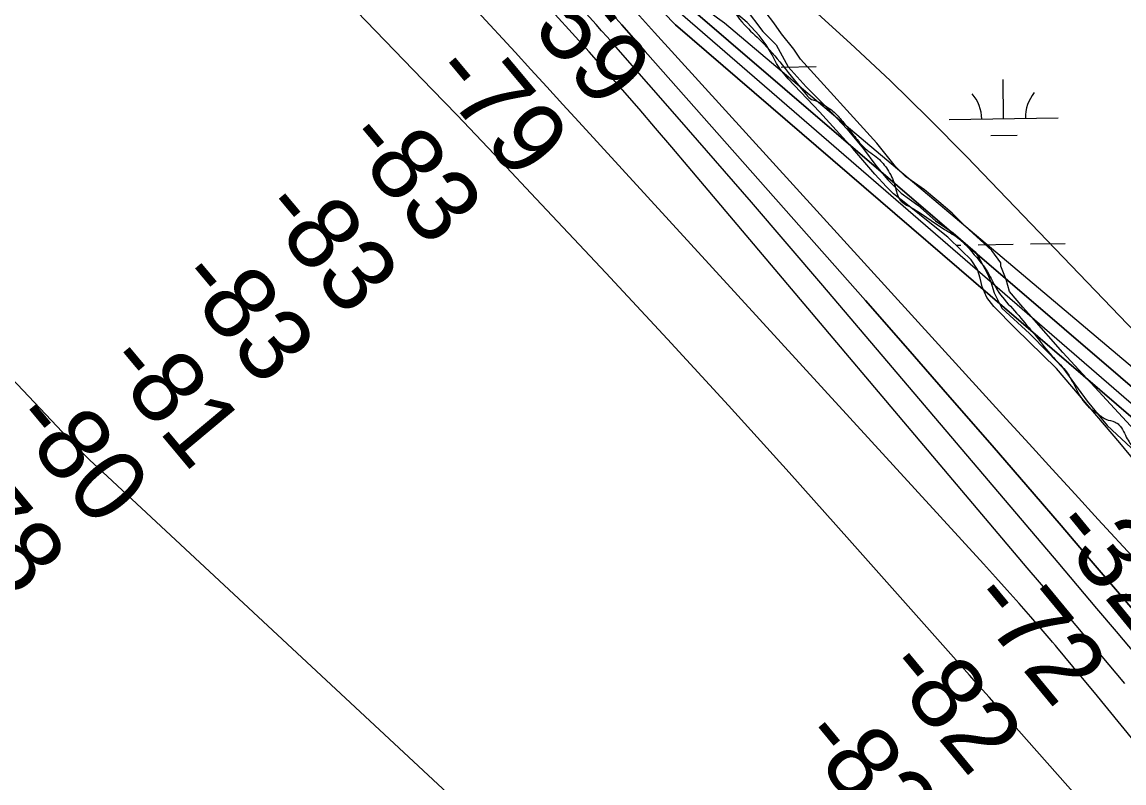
# Model space of a CAD drawing. Extents: x 3887375 to 3925618, y 296674 to 322633.
# Drawn here: x 3897913 to 3898925, y 309507 to 310205 of the extents above; entities that cross this region are included whole.
import ezdxf

# ---------------------------------------------------------------- set-up
doc = ezdxf.new("R2010")
doc.units = 0
for name, color, linetype in [('V-RIVR-EDGE', 7, 'Continuous'), ('V-RIVR-JETY', 7, 'Continuous'), ('V-RIVR-RANG', 7, 'Continuous'), ('V-TOPO-DPTH', 7, 'Continuous'), ('V-TOPO-MAJR', 7, 'Continuous'), ('V-TOPO-MINR', 7, 'Continuous'), ('V-TOPO-WATR', 7, 'Continuous'), ('V-WETL-SWMP', 7, 'Continuous')]:
    doc.layers.add(name, color=color, linetype=linetype)

msp = doc.modelspace()

# ---------------------------------------------------------------- linework, layer by layer
at = {"layer": 'V-RIVR-EDGE'}
for points in [[(3896115.8, 312736.3), (3896123.6, 312723.7), (3896129.9, 312714.4), (3896135.6, 312703.7), (3896139.5, 312690.4), (3896139.8, 312681.4), (3896138.2, 312674.8), (3896136.8, 312674.1), (3896128.5, 312683.1), (3896119.6, 312696.5), (3896111.3, 312706.8), (3896107.3, 312707.8), (3896105, 312706.5), (3896104.3, 312701.1), (3896107.9, 312688.8), (3896111.2, 312681.2), (3896123.5, 312667.2), (3896140.7, 312647.2), (3896161, 312617.2), (3896188.5, 312584.9), (3896210, 312563.2), (3896237.6, 312538.5), (3896253.5, 312524.9), (3896271.4, 312512.5), (3896287.7, 312501.8), (3896299, 312494.8), (3896307, 312486.8), (3896325.8, 312456.2), (3896335.8, 312438.5), (3896350.7, 312424.2), (3896373.6, 312404.5), (3896404.8, 312381.8), (3896442, 312359.5), (3896468.9, 312343.4), (3896491.1, 312332.4), (3896500.1, 312327.1), (3896508.4, 312318.7), (3896515.3, 312306.4), (3896528.3, 312284.4), (3896534.9, 312271.8), (3896552.8, 312258.8), (3896583, 312239.7), (3896613.6, 312220), (3896639.8, 312198.7), (3896665.3, 312175.7), (3896698.5, 312153), (3896718.4, 312139), (3896747, 312114.6), (3896768.2, 312094.3), (3896793.7, 312068.3), (3896812.7, 312048.3), (3896828.9, 312030), (3896844.5, 312006.3), (3896867.4, 311982.3), (3896895.9, 311956), (3896949, 311910), (3896976.5, 311885.6), (3896985.2, 311878.6), (3896997.8, 311872.9), (3897005.4, 311870.2), (3897020, 311862.9), (3897041.6, 311845.9), (3897061.2, 311830.9), (3897070.1, 311823.9), (3897078.8, 311813.9), (3897087.7, 311797.5), (3897092.3, 311785.6), (3897097, 311776.9), (3897111.2, 311756.3), (3897119.5, 311747.3), (3897129.5, 311738.6), (3897149.4, 311722.6), (3897170.9, 311704.6), (3897186.2, 311690.6), (3897201.8, 311670.2), (3897228.6, 311633.3), (3897264.7, 311581.6), (3897280, 311565), (3897305.2, 311540), (3897328.4, 311515.6), (3897360.9, 311485.9), (3897388.8, 311458.3), (3897419.3, 311434.3), (3897433.9, 311420.3), (3897454.5, 311394.6), (3897475, 311368.3), (3897490.6, 311354.6), (3897505.6, 311336.6), (3897515.8, 311319.6), (3897527.8, 311305.3), (3897546.7, 311288.3), (3897564.6, 311280.6), (3897578.2, 311271.3), (3897592.8, 311257.9), (3897613.1, 311238.6), (3897630.3, 311218.9), (3897644.6, 311200.6), (3897648.9, 311196.6), (3897654.9, 311195.9), (3897664.8, 311187.9), (3897681.4, 311173.9), (3897696, 311156.2), (3897728.2, 311123.2), (3897747.7, 311099.3), (3897753.7, 311088.3), (3897756.7, 311085.6), (3897762.6, 311082.9), (3897779.6, 311067.6), (3897798.5, 311046.9), (3897815.4, 311028.6), (3897832, 311014.6), (3897852.2, 310999.9), (3897867.8, 310985.6), (3897880.8, 310970.2), (3897894, 310949.2), (3897907.6, 310928.6), (3897922.2, 310908.3), (3897948, 310879.6), (3897967.3, 310856.6), (3897987.8, 310835.3), (3898011.7, 310813.3), (3898048.6, 310785.3), (3898064.5, 310774.2), (3898081.4, 310759.2), (3898099.7, 310738.9), (3898112.9, 310724.6), (3898123.2, 310708.6), (3898130.8, 310696.3), (3898136.8, 310688.9), (3898147.4, 310677.3), (3898160, 310664.3), (3898168.9, 310655.3), (3898196.5, 310623.6), (3898206.1, 310609.3), (3898214, 310600.6), (3898230.3, 310582), (3898242.2, 310565.3), (3898262.4, 310541.3), (3898281.7, 310521.3), (3898296.6, 310506), (3898340.4, 310470.3), (3898350, 310459.3), (3898357, 310445.3), (3898373.6, 310426), (3898390.1, 310409.6), (3898399.4, 310404.6), (3898413.4, 310395.3), (3898421.7, 310387.3), (3898430, 310378.6), (3898436.6, 310363.3), (3898463.4, 310334.6), (3898482.3, 310314.6), (3898496.6, 310298.3), (3898513.2, 310279.7), (3898535.7, 310254.7), (3898547.3, 310242), (3898560.3, 310224.7), (3898576.5, 310203), (3898592.1, 310187.7), (3898611.3, 310166), (3898633.5, 310138.7), (3898638.2, 310134.4), (3898642.5, 310133), (3898652.1, 310127.7), (3898657.8, 310123.7), (3898665.4, 310115.7), (3898676.7, 310101.7), (3898686, 310090.7), (3898692.6, 310085.3), (3898699.2, 310080.3), (3898707.9, 310070), (3898714.5, 310056.4), (3898718.4, 310043.7), (3898720.4, 310041), (3898727.4, 310036.4), (3898760.3, 310015), (3898774.2, 310006), (3898785.5, 309994.3), (3898801.4, 309973.3), (3898808.7, 309959.4), (3898822.6, 309942.4), (3898837.9, 309924.7), (3898844.8, 309916.4), (3898858.7, 309899), (3898871.4, 309885.4), (3898894.5, 309850.4), (3898899.9, 309846.7), (3898908.5, 309840.7), (3898917.1, 309838), (3898920.4, 309835.7), (3898928.1, 309822.7), (3898935.4, 309812.7), (3898943.6, 309802.7), (3898951.9, 309787.7), (3898962.9, 309772.4), (3898972.5, 309757.4), (3898979.1, 309752.4), (3898987.1, 309749.1), (3898990.7, 309745.1), (3899002, 309727.8), (3899013.3, 309715.4), (3899031.2, 309696.4), (3899044.8, 309680.1), (3899055.7, 309665.5), (3899065, 309653.8), (3899074.6, 309640.1), (3899085.5, 309630.8), (3899093.8, 309628.1), (3899099.2, 309628.1), (3899103.2, 309626.1), (3899108.1, 309616.1), (3899114.7, 309606.4), (3899123.7, 309591.1), (3899128.3, 309582.8), (3899128.3, 309580.5), (3899127.6, 309569.2), (3899127.9, 309565.8), (3899132.9, 309561.5), (3899159.8, 309529.2), (3899191, 309497.2), (3899204.9, 309480.5), (3899212.2, 309470.2), (3899224.8, 309457.2), (3899244.7, 309437.5), (3899252.6, 309429.9), (3899261.9, 309422.9), (3899272.6, 309415.8), (3899279.5, 309406.5), (3899287.5, 309396.2), (3899300.1, 309376.5), (3899311.3, 309362.5), (3899327.9, 309343.2), (3899342.2, 309325.6), (3899360.1, 309304.6), (3899377.3, 309282.9), (3899414.5, 309240.6), (3899433.4, 309219.6), (3899447.3, 309203.9), (3899464.5, 309184.9), (3899479.1, 309166.9), (3899493.4, 309149.9)], [(3894498, 310522.4), (3894530, 310496.1), (3894553.8, 310474.7), (3894579.9, 310451.3), (3894614.8, 310419.2), (3894633.2, 310400.7), (3894662.8, 310372.4), (3894685.1, 310353.4), (3894692.4, 310347.1), (3894709.8, 310328.1), (3894746.6, 310285.3), (3894785.8, 310252.2), (3894809.6, 310225.9), (3894830.4, 310205.4), (3894852.7, 310189.9), (3894866.7, 310171.8), (3894915.2, 310120.3), (3894950.1, 310083.7), (3894971.4, 310062.8), (3894999, 310039.4), (3895025.2, 310017), (3895052.8, 309992.7), (3895093, 309952.3), (3895110.9, 309932.8), (3895141.4, 309903.1), (3895188.9, 309855.9), (3895222.8, 309821.3), (3895255.8, 309784.3), (3895319.2, 309722.5), (3895350.7, 309688.4), (3895358.4, 309676.3), (3895364.7, 309669.4), (3895374.9, 309663.1), (3895389, 309650.4), (3895410.8, 309628.1), (3895448.5, 309583.3), (3895480.5, 309554.1), (3895503.8, 309527.8), (3895533.8, 309499.5), (3895577.4, 309454.8), (3895606.9, 309425.5), (3895653.5, 309378.8), (3895685.9, 309349.1), (3895719.8, 309314.5), (3895749.4, 309285.8), (3895790.6, 309242.5), (3895837.1, 309195.8), (3895863.7, 309164.1), (3895900, 309127.6), (3895944.1, 309081.4), (3895955.7, 309070.7), (3895974.6, 309054.6), (3896002.3, 309033.1), (3896032.8, 309003.9), (3896062.8, 308972.3), (3896082.7, 308950.4), (3896119.5, 308911.9), (3896139.3, 308892.5), (3896152, 308889.5), (3896163.1, 308883.7), (3896167.9, 308873.9), (3896170.3, 308862.3), (3896184.4, 308844.3), (3896211, 308816), (3896224.1, 308810.2), (3896236.7, 308802.4), (3896249.8, 308786.8), (3896255.6, 308776.6), (3896270.6, 308766.4), (3896280.3, 308753.2), (3896295.8, 308737.2), (3896375.3, 308661.2), (3896425.2, 308610.1), (3896464.4, 308570.6), (3896519.6, 308515.6), (3896548.7, 308483), (3896563.2, 308467.5), (3896597.6, 308430.9), (3896635.9, 308396.4), (3896666.4, 308365.7), (3896681.4, 308349.6), (3896712.4, 308320.4), (3896746.3, 308287.3), (3896777.4, 308260), (3896801.6, 308235.7), (3896820.5, 308215.3), (3896842.8, 308195.3), (3896851.5, 308181.2), (3896882.5, 308148.6), (3896918.8, 308116.4), (3896962.9, 308074.6), (3896997.8, 308033.2), (3897029.2, 307998.6), (3897042.3, 307985), (3897083.5, 307945.6), (3897107.2, 307918.3), (3897123.2, 307898.8), (3897130, 307898.8), (3897142.1, 307893), (3897146, 307882.3), (3897149.9, 307874), (3897162.9, 307860.4), (3897188.6, 307833.1), (3897229.3, 307788.8), (3897267.6, 307752.3), (3897300.5, 307715.8), (3897334.4, 307680.3), (3897361.5, 307651.1), (3897384.8, 307628.2), (3897411.4, 307599), (3897445.8, 307563.4), (3897494.3, 307516.7), (3897543.2, 307462.7), (3897584.8, 307418.4), (3897609, 307394), (3897646.8, 307355.6), (3897678.8, 307323.9), (3897715.1, 307290.3), (3897752, 307253.3), (3897767, 307236.3), (3897837.7, 307158.4), (3897886.6, 307104.4), (3897936, 307048.4), (3897965.5, 307015.3), (3898010.6, 306970.1), (3898027.5, 306949.1), (3898045, 306936), (3898063.9, 306914.1), (3898089, 306882.5), (3898117.1, 306854.7), (3898160.2, 306801.2), (3898195.6, 306763.7), (3898235.8, 306719.9), (3898261.5, 306693.6), (3898297.3, 306650.8), (3898332.7, 306612.3), (3898369.9, 306568), (3898397.5, 306534.9), (3898422.2, 306505.8), (3898462.9, 306455.1), (3898495.3, 306417.2), (3898522, 306382.2), (3898601.4, 306284.3), (3898652.2, 306228.4), (3898693.4, 306177.3), (3898729.7, 306130.6), (3898777.1, 306074.1), (3898825.5, 306014.3), (3898848.8, 305986), (3898904, 305917.4), (3898957.2, 305854.7), (3898984.4, 305818.2), (3899049.7, 305744.7), (3899107.8, 305679.4), (3899129.1, 305651.7), (3899142.7, 305630.3), (3899156.2, 305611.8), (3899175.1, 305588), (3899224, 305529.6), (3899256, 305493.6), (3899288.9, 305449.3), (3899312.6, 305415.2), (3899375.6, 305336.9), (3899410.9, 305296), (3899442.8, 305252.2), (3899470.4, 305211.9), (3899531.4, 305133.5), (3899579.3, 305071.2), (3899616.1, 305026), (3899647.1, 304986.1), (3899690.7, 304931.1), (3899729.4, 304876.6), (3899753.6, 304846.9), (3899770.6, 304821.6), (3899817.5, 304755.5), (3899845.6, 304713.2), (3899868.3, 304677.2), (3899889.6, 304650.4), (3899911.4, 304623.6), (3899955.4, 304569.1), (3899987.4, 304526.8), (3900012.6, 304494.2), (3900025.6, 304476.2), (3900037.2, 304456.8), (3900061.9, 304431.9), (3900070.7, 304424.1), (3900074.5, 304414.4), (3900075, 304404.2), (3900073, 304397.9), (3900071.5, 304388.7), (3900071.5, 304383.8), (3900075.9, 304379), (3900087.1, 304374.1), (3900096.3, 304367.7), (3900108.4, 304362.4), (3900117.1, 304353.6), (3900140.8, 304326.3), (3900165.5, 304299.1), (3900226.1, 304227.6), (3900277.9, 304164.3), (3900320, 304105.9), (3900352.4, 304062.6), (3900384.4, 304023.2), (3900411.5, 303988.2), (3900438.1, 303954.1), (3900462.8, 303926.8), (3900556.2, 303812.5), (3900597.9, 303762.9), (3900633.7, 303716.6), (3900652.6, 303691.3), (3900702, 303626.6), (3900774.6, 303530.8), (3900849.1, 303437.3), (3900903.4, 303371.2), (3900928.1, 303343.4), (3900948.9, 303317.6), (3901001.2, 303258.3), (3901038.9, 303216.9), (3901074.8, 303173.1), (3901092.2, 303147.3), (3901171.6, 303050.5), (3901205, 303008.6), (3901238.4, 302968.2), (3901274.7, 302927.8), (3901303.3, 302893.8), (3901344, 302847.5), (3901366.7, 302816.4), (3901404.5, 302770.2), (3901454.4, 302715.2), (3901507.2, 302659.2), (3901551.7, 302608.1), (3901584.7, 302570.6), (3901650, 302491.3), (3901681, 302443.6), (3901717.8, 302388.2), (3901785.5, 302298.2), (3901789.5, 302293.3)]]:
    msp.add_spline(points, degree=3, dxfattribs=at)
at = {"layer": 'V-RIVR-JETY'}
for points in [[(3898577.2, 310218.1), (3898593.4, 310196.7), (3898605.6, 310184.5), (3898616.8, 310164.2), (3898633.1, 310145.9), (3898652.4, 310126.6), (3898670.7, 310107.3), (3898685.9, 310089), (3898697.1, 310073.7), (3898708.3, 310060.5), (3898720.5, 310048.3), (3898735.7, 310037.2), (3898752, 310022.9), (3898768.2, 310011.8), (3898788.5, 309994.5), (3898792.6, 309987.4), (3898799.7, 309974.2), (3898802.8, 309967), (3898805.8, 309956.9), (3898812.9, 309942.7), (3898838.3, 309919.3), (3898855.6, 309902), (3898868.8, 309887.8), (3898891.2, 309857.3), (3898909.5, 309834.9), (3898931.8, 309814.6)], [(3898942, 309822.7), (3898868.8, 309902), (3898840.4, 309934.5), (3898832.2, 309943.7), (3898820, 309957.9), (3898817, 309969.1), (3898811.9, 309981.3), (3898811.9, 309984.3), (3898803.8, 309995.5), (3898779.4, 310017.9), (3898767.2, 310030), (3898755, 310040.2), (3898741.8, 310051.4), (3898735.7, 310055.5), (3898724.5, 310063.6), (3898715.4, 310072.7), (3898698.1, 310094.1), (3898628, 310171.3), (3898621.9, 310180.5), (3898610.7, 310194.7), (3898603.6, 310204.8), (3898596.5, 310214)]]:
    msp.add_lwpolyline(points, dxfattribs=at)
at = {"layer": 'V-TOPO-DPTH'}
for points in [[(3898945.1, 309652), (3898919.2, 309682.5), (3898893.2, 309712.8), (3898867.3, 309743.1), (3898842.5, 309772), (3898803.9, 309816.6), (3898765.3, 309861.1), (3898726.5, 309905.5), (3898687.6, 309949.8), (3898485.5, 310178.5), (3898474.7, 310190.7), (3898463.9, 310202.9), (3898453, 310215.1), (3898442.1, 310227.3), (3898384.5, 310291.4), (3898344.7, 310335.6), (3898304.9, 310379.8), (3898265, 310423.8), (3898225, 310467.8), (3897965.8, 310752.8)], [(3897965.8, 310752.8), (3898225, 310467.8), (3898265, 310423.8), (3898304.9, 310379.8), (3898344.7, 310335.6), (3898384.5, 310291.4), (3898442.1, 310227.3), (3898453, 310215.1), (3898463.9, 310202.9), (3898474.7, 310190.7), (3898485.5, 310178.5), (3898687.6, 309949.8), (3898726.5, 309905.5), (3898765.3, 309861.1), (3898803.9, 309816.6), (3898842.5, 309772), (3898867.3, 309743.1), (3898893.2, 309712.8), (3898919.2, 309682.5), (3898945.1, 309652)], [(3899686.2, 308933.2), (3899549.1, 309098.8), (3899533, 309118.6), (3899517.2, 309138.6), (3899501.6, 309159), (3899486.4, 309179.5), (3899361.7, 309350.3), (3899308.5, 309422.5), (3899255, 309494.5), (3899200.9, 309566), (3899146.4, 309637.2), (3899056.5, 309753.8), (3899046.5, 309766.3), (3899036.2, 309778.6), (3899025.5, 309790.5), (3898510.2, 310233), (3898505.7, 310237.7), (3898501.2, 310242.5), (3898496.8, 310247.3), (3898150, 310629.3)], [(3898150, 310629.3), (3898496.8, 310247.3), (3898501.2, 310242.5), (3898505.7, 310237.7), (3898510.2, 310233), (3899025.5, 309790.5), (3899036.2, 309778.6), (3899046.5, 309766.3), (3899056.5, 309753.8), (3899146.4, 309637.2), (3899200.9, 309566), (3899255, 309494.5), (3899308.5, 309422.5), (3899361.7, 309350.3), (3899486.4, 309179.5), (3899501.6, 309159), (3899517.2, 309138.6), (3899533, 309118.6), (3899549.1, 309098.8), (3899686.2, 308933.2)], [(3898936, 309711.3), (3898901.5, 309748.8), (3898880.4, 309771.8), (3898859.2, 309794.9), (3898838.1, 309818), (3898817, 309841.1), (3898494.1, 310195.7), (3898477.4, 310214.2), (3898460.7, 310232.7), (3898444, 310251.2), (3898356.1, 310348.9), (3898295.4, 310416.1), (3898234.6, 310483.3), (3898173.6, 310550.2), (3898112.4, 310617.1)], [(3898112.4, 310617.1), (3898173.6, 310550.2), (3898234.6, 310483.3), (3898295.4, 310416.1), (3898356.1, 310348.9), (3898444, 310251.2), (3898460.7, 310232.7), (3898477.4, 310214.2), (3898494.1, 310195.7), (3898817, 309841.1), (3898838.1, 309818), (3898859.2, 309794.9), (3898880.4, 309771.8), (3898901.5, 309748.8), (3898936, 309711.3)], [(3899016.7, 309835.9), (3898780.7, 310081.6), (3898745.8, 310117), (3898710.3, 310151.8), (3898674, 310185.8), (3898637.1, 310219.1), (3898591.8, 310259), (3898577.1, 310272), (3898562.5, 310285), (3898547.9, 310298.1), (3898533.4, 310311.2), (3898468.4, 310370), (3898421.4, 310412.5), (3898374.4, 310455), (3898327.3, 310497.4), (3898280.2, 310539.9), (3898226.5, 310588.3)], [(3898165.3, 310585.9), (3898212.4, 310534.2), (3898259.4, 310482.3), (3898470, 310249.3), (3898480.7, 310237.5), (3898491.4, 310225.9), (3898502.3, 310214.3), (3898513.2, 310202.8), (3898975.1, 309805.6)], [(3898165.3, 310585.9), (3898212.4, 310534.2), (3898259.4, 310482.3), (3898470, 310249.3), (3898480.7, 310237.5), (3898491.4, 310225.9), (3898502.3, 310214.3), (3898513.2, 310202.8), (3898975.1, 309805.6)]]:
    msp.add_lwpolyline(points, dxfattribs=at)
at = {"layer": 'V-TOPO-MAJR'}
msp.add_lwpolyline([(3898936, 309624.8), (3898918.2, 309645.9), (3898900.3, 309666.9), (3898882.4, 309688), (3898864.5, 309709.1), (3898648.6, 309963.4), (3898615.9, 310001.7), (3898583, 310040), (3898550, 310078.1), (3898516.9, 310116), (3898460.6, 310180.3), (3898455.6, 310186.1), (3898450.5, 310191.8), (3898445.4, 310197.5), (3898440.3, 310203.2), (3898413.2, 310233.5), (3898394.5, 310254.3), (3898375.8, 310275.1), (3898357.1, 310295.9), (3898338.4, 310316.6), (3897943.8, 310754.4)], dxfattribs=at)
at = {"layer": 'V-TOPO-MINR'}
for points in [[(3898945.1, 309652), (3898919.2, 309682.5), (3898893.2, 309712.8), (3898867.3, 309743.1), (3898842.5, 309772), (3898803.9, 309816.6), (3898765.3, 309861.1), (3898726.5, 309905.5), (3898687.6, 309949.8), (3898485.5, 310178.5), (3898474.7, 310190.7), (3898463.9, 310202.9), (3898453, 310215.1), (3898442.1, 310227.3), (3898384.5, 310291.4), (3898344.7, 310335.6), (3898304.9, 310379.8), (3898265, 310423.8), (3898225, 310467.8), (3897965.8, 310752.8)], [(3899015.4, 309818.8), (3898558.3, 310204.4), (3898551.9, 310209), (3898545.6, 310213.7), (3898544.6, 310214.4), (3898539, 310218.9), (3898533.5, 310223.5), (3898528.2, 310228.4), (3898523.1, 310233.5), (3898515.4, 310241.4), (3898513.1, 310243.8), (3898510.8, 310246.3), (3898095.6, 310702.3)], [(3899686.2, 308933.2), (3899549.1, 309098.8), (3899533, 309118.6), (3899517.2, 309138.6), (3899501.6, 309159), (3899486.4, 309179.5), (3899361.7, 309350.3), (3899308.5, 309422.5), (3899255, 309494.5), (3899200.9, 309566), (3899146.4, 309637.2), (3899056.5, 309753.8), (3899046.5, 309766.3), (3899036.2, 309778.6), (3899025.5, 309790.5), (3898510.2, 310233), (3898505.7, 310237.7), (3898501.2, 310242.5), (3898496.8, 310247.3), (3898150, 310629.3)], [(3899238.1, 309092), (3898819.1, 309565.3), (3898810.1, 309575.4), (3898801.2, 309585.5), (3898792.2, 309595.6), (3898783.3, 309605.7), (3898673.1, 309729.8), (3898617.7, 309791.7), (3898562, 309853.3), (3898505.8, 309914.3), (3898449.2, 309975.1), (3898380.5, 310048.3), (3898358, 310072.2), (3898335.4, 310096), (3898312.7, 310119.8), (3898289.9, 310143.5), (3898203.3, 310233.4), (3898137.5, 310302.3), (3898072.1, 310371.6), (3898007.4, 310441.5), (3897943.1, 310511.8), (3897848, 310616.9)], [(3898936, 309711.3), (3898901.5, 309748.8), (3898880.4, 309771.8), (3898859.2, 309794.9), (3898838.1, 309818), (3898817, 309841.1), (3898494.1, 310195.7), (3898477.4, 310214.2), (3898460.7, 310232.7), (3898444, 310251.2), (3898356.1, 310348.9), (3898295.4, 310416.1), (3898234.6, 310483.3), (3898173.6, 310550.2), (3898112.4, 310617.1)], [(3898926, 309598.1), (3898903.6, 309624.6), (3898881.1, 309651.2), (3898858.7, 309677.8), (3898836.2, 309704.3), (3898525, 310072.7), (3898510, 310090.4), (3898494.9, 310108), (3898479.8, 310125.6), (3898464.6, 310143.1), (3898449.3, 310160.6), (3898433.9, 310178), (3898418.3, 310195.2), (3898402.7, 310212.4), (3898050.8, 310595.8)], [(3899818.9, 308745.4), (3899546.6, 309073.5), (3899524.8, 309100.4), (3899503.3, 309127.5), (3899482.4, 309155), (3899461.8, 309182.9), (3899222.5, 309512.5), (3899190.6, 309556.1), (3899158.5, 309599.5), (3899126, 309642.7), (3899093.2, 309685.7), (3899039.4, 309755.7), (3899033.3, 309763.4), (3899026.9, 309771), (3899020.4, 309778.3), (3898506.2, 310223.5), (3898498.5, 310231.7), (3898490.8, 310240), (3898483.3, 310248.3), (3898204.6, 310556), (3898167.8, 310596.5)], [(3898975.1, 309805.6), (3898513.2, 310202.8), (3898502.3, 310214.3), (3898491.4, 310225.9), (3898480.7, 310237.5), (3898470, 310249.3), (3898259.4, 310482.3), (3898212.4, 310534.2), (3898165.3, 310585.9)], [(3898934.7, 309544.7), (3898922.5, 309559.7), (3898910.3, 309574.7), (3898897.9, 309589.7), (3898885.6, 309604.7), (3898863.5, 309631.3), (3898862.1, 309632.9), (3898859.4, 309636.1), (3898858.1, 309637.6), (3898839.4, 309659.2), (3898828.7, 309671.4), (3898817.9, 309683.7), (3898807, 309695.8), (3898796, 309707.9), (3898424.5, 310113.8), (3898409.9, 310129.8), (3898395.2, 310145.8), (3898380.5, 310161.8), (3898365.9, 310177.8), (3898296.9, 310252.8)], [(3897601.1, 310198.2), (3897945.3, 309834.1), (3897949.7, 309829.5), (3897954.1, 309824.9), (3897958.5, 309820.3), (3897963, 309815.7), (3897968.4, 309810.2), (3897970.2, 309808.4), (3897973.7, 309804.9), (3897975.5, 309803.2), (3897979.1, 309799.7), (3897982.8, 309796.3), (3898357.6, 309447.4)]]:
    msp.add_lwpolyline(points, dxfattribs=at)
at = {"layer": 'V-TOPO-WATR'}
msp.add_lwpolyline([(3899016.7, 309835.9), (3898780.7, 310081.6), (3898745.8, 310117), (3898710.3, 310151.8), (3898674, 310185.8), (3898637.1, 310219.1), (3898591.8, 310259), (3898577.1, 310272), (3898562.5, 310285), (3898547.9, 310298.1), (3898533.4, 310311.2), (3898468.4, 310370), (3898421.4, 310412.5), (3898374.4, 310455), (3898327.3, 310497.4), (3898280.2, 310539.9), (3898226.5, 310588.3)], dxfattribs=at)
at = {"layer": 'V-WETL-SWMP'}
for p, q in [((3898610.4, 310163.9), (3898642.4, 310164.5)), ((3898814.6, 310116.7), (3898814, 310152.7)), ((3898764.6, 310115.8), (3898864.6, 310117.5)), ((3898802.9, 310101.1), (3898826.9, 310101.5)), ((3898791.2, 310000.8), (3898823.2, 310001.4)), ((3898839.2, 310001.7), (3898871.2, 310002.2)), ((3898771, 310000.5), (3898775.2, 310000.6))]:
    msp.add_line(p, q, dxfattribs=at)
msp.add_lwpolyline([(3898984.7, 309742.2), (3898921.3, 309819), (3898863.2, 309887.2), (3898825.3, 309924.3), (3898805.7, 309944.1), (3898799.2, 309952.5), (3898794.8, 309962.3), (3898792.9, 309970.1), (3898790.7, 309978.1), (3898784.9, 309987), (3898775.9, 309995.8), (3898763.2, 310007.9), (3898748.2, 310019.7), (3898724.7, 310038.7), (3898713.4, 310047.8), (3898706.9, 310054.2), (3898696.3, 310065.8), (3898676.2, 310089.2), (3898645.4, 310123.1), (3898616.8, 310153.3), (3898609.6, 310161.8), (3898605.9, 310167.5), (3898601.9, 310175.2), (3898596.6, 310184.6), (3898590.1, 310193.2), (3898579, 310205.1), (3898559.6, 310221.4)], dxfattribs=at)
for centre, start, end in [((3898759.3, 310116.2), 0.2115, 41.7552), ((3898869.8, 310118.1), 140.2115, 181.7552)]:
    msp.add_arc(centre, 35.2, start, end, dxfattribs=at)

# ---------------------------------------------------------------- texts
at = {"layer": 'V-RIVR-RANG'}
for s, rotation, p in [('-59', 309.8958, (3898361.6, 310222.1)), ('-79', 309.8958, (3898285.8, 310156.9)), ('-83', 309.8958, (3898206.4, 310096)), ('-83', 309.8958, (3898129.5, 310032.1)), ('-83', 309.8958, (3898052.6, 309968.1)), ('-81', 309.8958, (3897986.7, 309891)), ('-80', 309.8958, (3897900.4, 309838.4)), ('-78', 309.8958, (3897824, 309773.8)), ('-32', 309.2683, (3898855.3, 309739.7)), ('-72', 309.5528, (3898779.9, 309673.4)), ('-82', 309.5528, (3898702.3, 309610.3)), ('-82', 309.5528, (3898625, 309546.8))]:
    msp.add_text(s, height=67, rotation=rotation, dxfattribs=at).set_placement(p)

doc.saveas('drawing.dxf')
